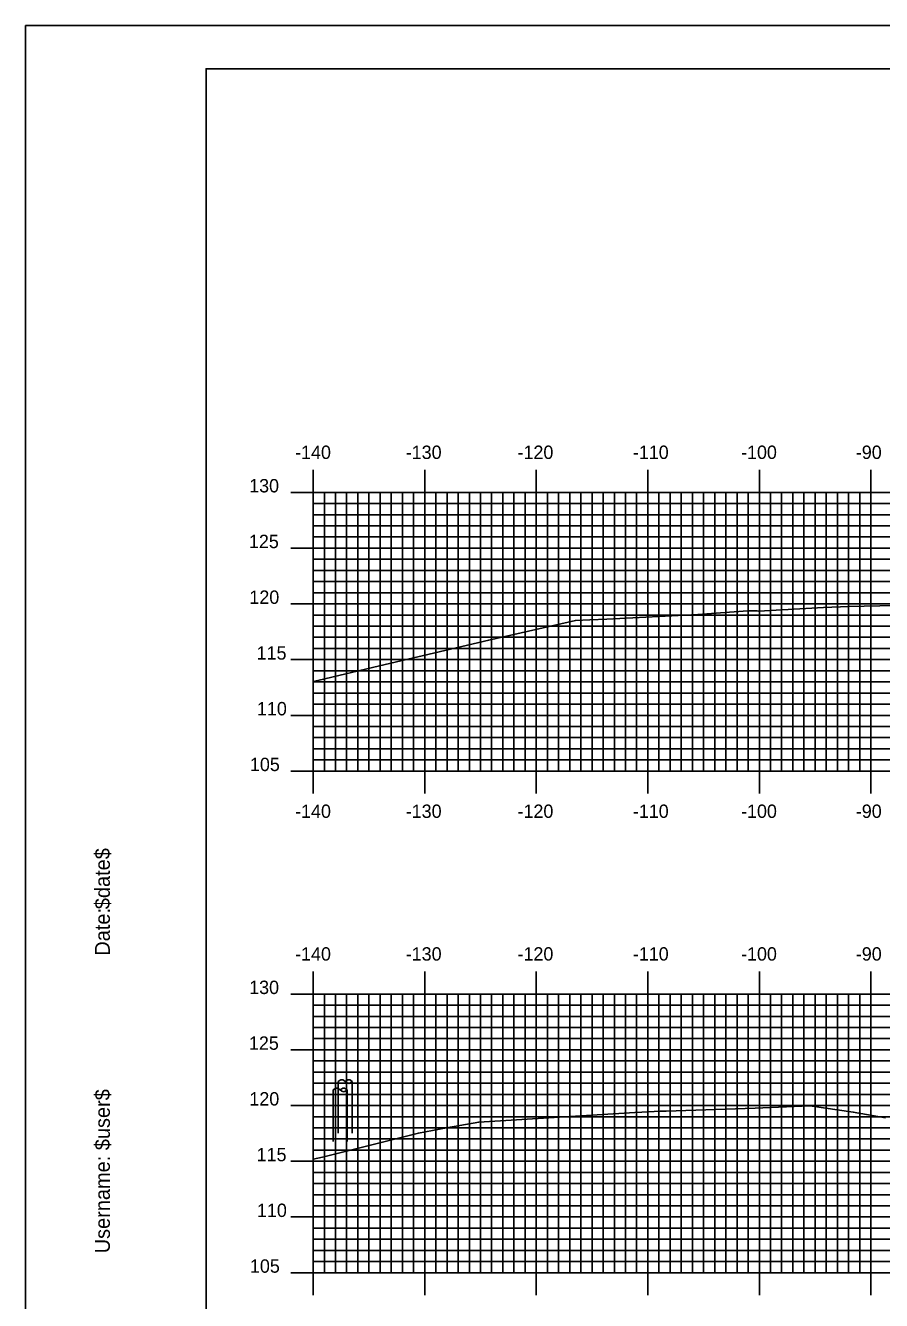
# Model space of a CAD drawing. Extents: x 1685979 to 1686323, y 461260 to 461480.
# Drawn here: x 1685979.5 to 1686056.2, y 461365.6 to 461480 of the extents above; entities that cross this region are included whole.
import ezdxf

# ---------------------------------------------------------------- set-up
doc = ezdxf.new("R2010")
doc.units = 0
for name, color, linetype in [('BORDER', 7, 'Continuous'), ('H_V ANNOTATION', 7, 'Continuous'), ('M_Roadway_Centerline', 7, 'Continuous'), ('M_Utilities_Pole_StreetLight', 7, 'Continuous'), ('MAJOR', 7, 'Continuous'), ('MINOR', 7, 'Continuous'), ('PLOT BOUNDARY', 7, 'Continuous'), ('S_Roadway_Centerline', 7, 'Continuous'), ('S_Utilities_Pole_StreetLight', 7, 'Continuous')]:
    doc.layers.add(name, color=color, linetype=linetype)

msp = doc.modelspace()

# ---------------------------------------------------------------- linework, layer by layer
at = {"layer": 'BORDER'}
msp.add_lwpolyline([(1685995.66, 461266.07), (1686315.66, 461266.07), (1686315.66, 461476.07), (1685995.66, 461476.07)], close=True, dxfattribs=at)
at = {"layer": 'M_Utilities_Pole_StreetLight'}
for p, q in [((1686007.05, 461384.47), (1686007.21, 461384.58)), ((1686007.05, 461379.85), (1686007.05, 461384.47)), ((1686007.52, 461384.58), (1686007.68, 461384.47)), ((1686007.83, 461384.58), (1686007.68, 461384.47)), ((1686007.68, 461384.47), (1686007.83, 461384.36)), ((1686008.3, 461384.47), (1686008.15, 461384.58)), ((1686008.15, 461384.36), (1686008.3, 461384.47)), ((1686008.3, 461379.85), (1686008.3, 461384.47))]:
    msp.add_line(p, q, dxfattribs=at)
for centre, start, end in [((1686007.36, 461384.36), 90, 125.2644), ((1686007.36, 461384.36), 54.7356, 90), ((1686007.99, 461384.36), 90, 125.2644), ((1686007.99, 461384.36), 54.7356, 90), ((1686007.99, 461384.58), 234.7356, 270), ((1686007.99, 461384.58), 270, 305.2644)]:
    msp.add_arc(centre, 0.271, start, end, dxfattribs=at)
at = {"layer": 'MAJOR'}
for p, q in [((1686005.26, 461440.08), (1686005.26, 461438.07)), ((1686015.26, 461440.08), (1686015.26, 461438.07)), ((1686025.26, 461440.08), (1686025.26, 461438.07)), ((1686035.26, 461440.08), (1686035.26, 461438.07)), ((1686045.26, 461440.08), (1686045.26, 461438.07)), ((1686055.26, 461440.08), (1686055.26, 461438.07)), ((1686003.25, 461438.07), (1686005.26, 461438.07)), ((1686005.26, 461438.07), (1686285.26, 461438.07)), ((1686005.26, 461413.07), (1686005.26, 461438.07)), ((1686005.26, 461413.07), (1686005.26, 461438.07)), ((1686005.26, 461438.07), (1686285.26, 461438.07)), ((1686015.26, 461413.07), (1686015.26, 461438.07)), ((1686025.26, 461413.07), (1686025.26, 461438.07)), ((1686035.26, 461413.07), (1686035.26, 461438.07)), ((1686045.26, 461413.07), (1686045.26, 461438.07)), ((1686055.26, 461413.07), (1686055.26, 461438.07)), ((1686003.25, 461433.07), (1686005.26, 461433.07)), ((1686005.26, 461433.07), (1686285.26, 461433.07)), ((1686003.25, 461428.07), (1686005.26, 461428.07)), ((1686005.26, 461428.07), (1686285.26, 461428.07)), ((1686003.25, 461423.07), (1686005.26, 461423.07)), ((1686005.26, 461423.07), (1686285.26, 461423.07)), ((1686003.25, 461418.07), (1686005.26, 461418.07)), ((1686005.26, 461418.07), (1686285.26, 461418.07)), ((1686003.25, 461413.07), (1686005.26, 461413.07)), ((1686005.26, 461413.07), (1686285.26, 461413.07)), ((1686005.26, 461413.07), (1686285.26, 461413.07)), ((1686005.26, 461411.07), (1686005.26, 461413.07)), ((1686015.26, 461411.07), (1686015.26, 461413.07)), ((1686025.26, 461411.07), (1686025.26, 461413.07)), ((1686035.26, 461411.07), (1686035.26, 461413.07)), ((1686045.26, 461411.07), (1686045.26, 461413.07)), ((1686055.26, 461411.07), (1686055.26, 461413.07)), ((1686005.26, 461395.08), (1686005.26, 461393.07)), ((1686015.26, 461395.08), (1686015.26, 461393.07)), ((1686025.26, 461395.08), (1686025.26, 461393.07)), ((1686035.26, 461395.08), (1686035.26, 461393.07)), ((1686045.26, 461395.08), (1686045.26, 461393.07)), ((1686055.26, 461395.08), (1686055.26, 461393.07)), ((1686003.25, 461393.07), (1686005.26, 461393.07)), ((1686005.26, 461393.07), (1686285.26, 461393.07)), ((1686005.26, 461368.07), (1686005.26, 461393.07)), ((1686005.26, 461368.07), (1686005.26, 461393.07)), ((1686005.26, 461393.07), (1686285.26, 461393.07)), ((1686015.26, 461368.07), (1686015.26, 461393.07)), ((1686025.26, 461368.07), (1686025.26, 461393.07)), ((1686035.26, 461368.07), (1686035.26, 461393.07)), ((1686045.26, 461368.07), (1686045.26, 461393.07)), ((1686055.26, 461368.07), (1686055.26, 461393.07)), ((1686003.25, 461388.07), (1686005.26, 461388.07)), ((1686005.26, 461388.07), (1686285.26, 461388.07)), ((1686003.25, 461383.07), (1686005.26, 461383.07)), ((1686005.26, 461383.07), (1686285.26, 461383.07)), ((1686003.25, 461378.07), (1686005.26, 461378.07)), ((1686005.26, 461378.07), (1686285.26, 461378.07)), ((1686003.25, 461373.07), (1686005.26, 461373.07)), ((1686005.26, 461373.07), (1686285.26, 461373.07)), ((1686003.25, 461368.07), (1686005.26, 461368.07)), ((1686005.26, 461368.07), (1686285.26, 461368.07)), ((1686005.26, 461368.07), (1686285.26, 461368.07)), ((1686005.26, 461366.07), (1686005.26, 461368.07)), ((1686015.26, 461366.07), (1686015.26, 461368.07)), ((1686025.26, 461366.07), (1686025.26, 461368.07)), ((1686035.26, 461366.07), (1686035.26, 461368.07)), ((1686045.26, 461366.07), (1686045.26, 461368.07)), ((1686055.26, 461366.07), (1686055.26, 461368.07))]:
    msp.add_line(p, q, dxfattribs=at)
at = {"layer": 'MINOR'}
for p, q in [((1686005.26, 461437.07), (1686285.26, 461437.07)), ((1686005.26, 461437.07), (1686007.26, 461437.07)), ((1686006.26, 461413.07), (1686006.26, 461438.07)), ((1686007.26, 461413.07), (1686007.26, 461438.07)), ((1686008.26, 461413.07), (1686008.26, 461438.07)), ((1686009.26, 461413.07), (1686009.26, 461438.07)), ((1686010.26, 461413.07), (1686010.26, 461438.07)), ((1686011.26, 461413.07), (1686011.26, 461438.07)), ((1686012.26, 461413.07), (1686012.26, 461438.07)), ((1686013.26, 461413.07), (1686013.26, 461438.07)), ((1686014.26, 461413.07), (1686014.26, 461438.07)), ((1686016.26, 461413.07), (1686016.26, 461438.07)), ((1686017.26, 461413.07), (1686017.26, 461438.07)), ((1686018.26, 461413.07), (1686018.26, 461438.07)), ((1686019.26, 461413.07), (1686019.26, 461438.07)), ((1686020.26, 461413.07), (1686020.26, 461438.07)), ((1686021.26, 461413.07), (1686021.26, 461438.07)), ((1686022.26, 461413.07), (1686022.26, 461438.07)), ((1686023.26, 461413.07), (1686023.26, 461438.07)), ((1686024.26, 461413.07), (1686024.26, 461438.07)), ((1686026.26, 461413.07), (1686026.26, 461438.07)), ((1686027.26, 461413.07), (1686027.26, 461438.07)), ((1686028.26, 461413.07), (1686028.26, 461438.07)), ((1686029.26, 461413.07), (1686029.26, 461438.07)), ((1686030.26, 461413.07), (1686030.26, 461438.07)), ((1686031.26, 461413.07), (1686031.26, 461438.07)), ((1686032.26, 461413.07), (1686032.26, 461438.07)), ((1686033.26, 461413.07), (1686033.26, 461438.07)), ((1686034.26, 461413.07), (1686034.26, 461438.07)), ((1686036.26, 461413.07), (1686036.26, 461438.07)), ((1686037.26, 461413.07), (1686037.26, 461438.07)), ((1686038.26, 461413.07), (1686038.26, 461438.07)), ((1686039.26, 461413.07), (1686039.26, 461438.07)), ((1686040.26, 461413.07), (1686040.26, 461438.07)), ((1686041.26, 461413.07), (1686041.26, 461438.07)), ((1686042.26, 461413.07), (1686042.26, 461438.07)), ((1686043.26, 461413.07), (1686043.26, 461438.07)), ((1686044.26, 461413.07), (1686044.26, 461438.07)), ((1686046.26, 461413.07), (1686046.26, 461438.07)), ((1686047.26, 461413.07), (1686047.26, 461438.07)), ((1686048.26, 461413.07), (1686048.26, 461438.07)), ((1686049.26, 461413.07), (1686049.26, 461438.07)), ((1686050.26, 461413.07), (1686050.26, 461438.07)), ((1686051.26, 461413.07), (1686051.26, 461438.07)), ((1686052.26, 461413.07), (1686052.26, 461438.07)), ((1686053.26, 461413.07), (1686053.26, 461438.07)), ((1686054.26, 461413.07), (1686054.26, 461438.07)), ((1686005.26, 461436.07), (1686285.26, 461436.07)), ((1686005.26, 461436.07), (1686007.26, 461436.07)), ((1686005.26, 461435.07), (1686285.26, 461435.07)), ((1686005.26, 461435.07), (1686007.26, 461435.07)), ((1686005.26, 461434.07), (1686285.26, 461434.07)), ((1686005.26, 461434.07), (1686007.26, 461434.07)), ((1686005.26, 461432.07), (1686285.26, 461432.07)), ((1686005.26, 461432.07), (1686007.26, 461432.07)), ((1686005.26, 461431.07), (1686285.26, 461431.07)), ((1686005.26, 461431.07), (1686007.26, 461431.07)), ((1686005.26, 461430.07), (1686285.26, 461430.07)), ((1686005.26, 461430.07), (1686007.26, 461430.07)), ((1686005.26, 461429.07), (1686285.26, 461429.07)), ((1686005.26, 461429.07), (1686007.26, 461429.07)), ((1686005.26, 461427.07), (1686285.26, 461427.07)), ((1686005.26, 461427.07), (1686007.26, 461427.07)), ((1686005.26, 461426.07), (1686285.26, 461426.07)), ((1686005.26, 461426.07), (1686007.26, 461426.07)), ((1686005.26, 461425.07), (1686007.26, 461425.07)), ((1686005.26, 461425.07), (1686285.26, 461425.07)), ((1686005.26, 461424.07), (1686285.26, 461424.07)), ((1686005.26, 461424.07), (1686007.26, 461424.07)), ((1686005.26, 461422.07), (1686285.26, 461422.07)), ((1686005.26, 461422.07), (1686007.26, 461422.07)), ((1686005.26, 461421.07), (1686285.26, 461421.07)), ((1686005.26, 461421.07), (1686007.26, 461421.07)), ((1686005.26, 461420.07), (1686285.26, 461420.07)), ((1686005.26, 461420.07), (1686007.26, 461420.07)), ((1686005.26, 461419.07), (1686285.26, 461419.07)), ((1686005.26, 461419.07), (1686007.26, 461419.07)), ((1686005.26, 461417.07), (1686285.26, 461417.07)), ((1686005.26, 461417.07), (1686007.26, 461417.07)), ((1686005.26, 461416.07), (1686285.26, 461416.07)), ((1686005.26, 461416.07), (1686007.26, 461416.07)), ((1686005.26, 461415.07), (1686285.26, 461415.07)), ((1686005.26, 461415.07), (1686007.26, 461415.07)), ((1686005.26, 461414.07), (1686285.26, 461414.07)), ((1686005.26, 461414.07), (1686007.26, 461414.07)), ((1686006.26, 461368.07), (1686006.26, 461393.07)), ((1686007.26, 461368.07), (1686007.26, 461393.07)), ((1686008.26, 461368.07), (1686008.26, 461393.07)), ((1686009.26, 461368.07), (1686009.26, 461393.07)), ((1686010.26, 461368.07), (1686010.26, 461393.07)), ((1686011.26, 461368.07), (1686011.26, 461393.07)), ((1686012.26, 461368.07), (1686012.26, 461393.07)), ((1686013.26, 461368.07), (1686013.26, 461393.07)), ((1686014.26, 461368.07), (1686014.26, 461393.07)), ((1686016.26, 461368.07), (1686016.26, 461393.07)), ((1686017.26, 461368.07), (1686017.26, 461393.07)), ((1686018.26, 461368.07), (1686018.26, 461393.07)), ((1686019.26, 461368.07), (1686019.26, 461393.07)), ((1686020.26, 461368.07), (1686020.26, 461393.07)), ((1686021.26, 461368.07), (1686021.26, 461393.07)), ((1686022.26, 461368.07), (1686022.26, 461393.07)), ((1686023.26, 461368.07), (1686023.26, 461393.07)), ((1686024.26, 461368.07), (1686024.26, 461393.07)), ((1686026.26, 461368.07), (1686026.26, 461393.07)), ((1686027.26, 461368.07), (1686027.26, 461393.07)), ((1686028.26, 461368.07), (1686028.26, 461393.07)), ((1686029.26, 461368.07), (1686029.26, 461393.07)), ((1686030.26, 461368.07), (1686030.26, 461393.07)), ((1686031.26, 461368.07), (1686031.26, 461393.07)), ((1686032.26, 461368.07), (1686032.26, 461393.07)), ((1686033.26, 461368.07), (1686033.26, 461393.07)), ((1686034.26, 461368.07), (1686034.26, 461393.07)), ((1686036.26, 461368.07), (1686036.26, 461393.07)), ((1686037.26, 461368.07), (1686037.26, 461393.07)), ((1686038.26, 461368.07), (1686038.26, 461393.07)), ((1686039.26, 461368.07), (1686039.26, 461393.07)), ((1686040.26, 461368.07), (1686040.26, 461393.07)), ((1686041.26, 461368.07), (1686041.26, 461393.07)), ((1686042.26, 461368.07), (1686042.26, 461393.07)), ((1686043.26, 461368.07), (1686043.26, 461393.07)), ((1686044.26, 461368.07), (1686044.26, 461393.07)), ((1686046.26, 461368.07), (1686046.26, 461393.07)), ((1686047.26, 461368.07), (1686047.26, 461393.07)), ((1686048.26, 461368.07), (1686048.26, 461393.07)), ((1686049.26, 461368.07), (1686049.26, 461393.07)), ((1686050.26, 461368.07), (1686050.26, 461393.07)), ((1686051.26, 461368.07), (1686051.26, 461393.07)), ((1686052.26, 461368.07), (1686052.26, 461393.07)), ((1686053.26, 461368.07), (1686053.26, 461393.07)), ((1686054.26, 461368.07), (1686054.26, 461393.07)), ((1686005.26, 461392.07), (1686285.26, 461392.07)), ((1686005.26, 461392.07), (1686007.26, 461392.07)), ((1686005.26, 461391.07), (1686285.26, 461391.07)), ((1686005.26, 461391.07), (1686007.26, 461391.07)), ((1686005.26, 461390.07), (1686285.26, 461390.07)), ((1686005.26, 461390.07), (1686007.26, 461390.07)), ((1686005.26, 461389.07), (1686285.26, 461389.07)), ((1686005.26, 461389.07), (1686007.26, 461389.07)), ((1686005.26, 461387.07), (1686285.26, 461387.07)), ((1686005.26, 461387.07), (1686007.26, 461387.07)), ((1686005.26, 461386.07), (1686285.26, 461386.07)), ((1686005.26, 461386.07), (1686007.26, 461386.07)), ((1686005.26, 461385.07), (1686285.26, 461385.07)), ((1686005.26, 461385.07), (1686007.26, 461385.07)), ((1686005.26, 461384.07), (1686285.26, 461384.07)), ((1686005.26, 461384.07), (1686007.26, 461384.07)), ((1686005.26, 461382.07), (1686285.26, 461382.07)), ((1686005.26, 461382.07), (1686007.26, 461382.07)), ((1686005.26, 461381.07), (1686285.26, 461381.07)), ((1686005.26, 461381.07), (1686007.26, 461381.07)), ((1686005.26, 461380.07), (1686285.26, 461380.07)), ((1686005.26, 461380.07), (1686007.26, 461380.07)), ((1686005.26, 461379.07), (1686285.26, 461379.07)), ((1686005.26, 461379.07), (1686007.26, 461379.07)), ((1686005.26, 461377.07), (1686285.26, 461377.07)), ((1686005.26, 461377.07), (1686007.26, 461377.07)), ((1686005.26, 461376.07), (1686285.26, 461376.07)), ((1686005.26, 461376.07), (1686007.26, 461376.07)), ((1686005.26, 461375.07), (1686285.26, 461375.07)), ((1686005.26, 461375.07), (1686007.26, 461375.07)), ((1686005.26, 461374.07), (1686285.26, 461374.07)), ((1686005.26, 461374.07), (1686007.26, 461374.07)), ((1686005.26, 461372.07), (1686285.26, 461372.07)), ((1686005.26, 461372.07), (1686007.26, 461372.07)), ((1686005.26, 461371.07), (1686285.26, 461371.07)), ((1686005.26, 461371.07), (1686007.26, 461371.07)), ((1686005.26, 461370.07), (1686285.26, 461370.07)), ((1686005.26, 461370.07), (1686007.26, 461370.07)), ((1686005.26, 461369.07), (1686285.26, 461369.07)), ((1686005.26, 461369.07), (1686007.26, 461369.07))]:
    msp.add_line(p, q, dxfattribs=at)
at = {"layer": 'PLOT BOUNDARY'}
msp.add_lwpolyline([(1685979.47, 461259.95), (1686319.47, 461259.95), (1686319.47, 461479.95), (1685979.47, 461479.95)], close=True, dxfattribs=at)
at = {"layer": 'S_Roadway_Centerline'}
for points in [[(1686005.26, 461421.11), (1686005.69, 461421.2), (1686011.2, 461422.52), (1686021, 461424.82), (1686028.77, 461426.58), (1686030.05, 461426.63), (1686031.6, 461426.7), (1686039.75, 461427.13), (1686044.23, 461427.46), (1686045.05, 461427.44), (1686045.19, 461427.42), (1686051, 461427.74), (1686053.29, 461427.84), (1686057.45, 461427.93)], [(1686005.26, 461378.25), (1686006.09, 461378.45), (1686014.7, 461380.59), (1686017.22, 461381.07), (1686020.11, 461381.59), (1686034.1, 461382.43), (1686034.72, 461382.47), (1686036.37, 461382.57), (1686036.92, 461382.57), (1686044.87, 461382.83), (1686049.79, 461383.03), (1686053.68, 461382.48), (1686056.57, 461381.96)]]:
    msp.add_lwpolyline(points, dxfattribs=at)
at = {"layer": 'S_Utilities_Pole_StreetLight'}
for p, q in [((1686007.51, 461385.22), (1686007.67, 461385.33)), ((1686007.51, 461385.22), (1686007.67, 461385.33)), ((1686007.51, 461380.6), (1686007.51, 461385.22)), ((1686007.51, 461380.6), (1686007.51, 461385.22)), ((1686007.98, 461385.33), (1686008.14, 461385.22)), ((1686007.98, 461385.33), (1686008.14, 461385.22)), ((1686008.3, 461385.33), (1686008.14, 461385.22)), ((1686008.3, 461385.33), (1686008.14, 461385.22)), ((1686008.14, 461385.22), (1686008.3, 461385.11)), ((1686008.14, 461385.22), (1686008.3, 461385.11)), ((1686008.76, 461385.22), (1686008.61, 461385.33)), ((1686008.76, 461385.22), (1686008.61, 461385.33)), ((1686008.61, 461385.11), (1686008.76, 461385.22)), ((1686008.61, 461385.11), (1686008.76, 461385.22)), ((1686008.76, 461380.6), (1686008.76, 461385.22)), ((1686008.76, 461380.6), (1686008.76, 461385.22))]:
    msp.add_line(p, q, dxfattribs=at)
for centre, start, end in [((1686007.83, 461385.11), 90, 125.2644), ((1686007.83, 461385.11), 90, 125.2644), ((1686007.83, 461385.11), 54.7356, 90), ((1686007.83, 461385.11), 54.7356, 90), ((1686008.45, 461385.11), 90, 125.2644), ((1686008.45, 461385.11), 90, 125.2644), ((1686008.45, 461385.33), 234.7356, 270), ((1686008.45, 461385.33), 234.7356, 270), ((1686008.45, 461385.11), 54.7356, 90), ((1686008.45, 461385.11), 54.7356, 90), ((1686008.45, 461385.33), 270, 305.2644), ((1686008.45, 461385.33), 270, 305.2644)]:
    msp.add_arc(centre, 0.271, start, end, dxfattribs=at)

# ---------------------------------------------------------------- texts
at = {"layer": 'BORDER'}
for s, p in [('$date$', (1685987.03, 461400.68)), ('Date:', (1685987.03, 461396.51)), ('$user$', (1685987.03, 461379.06)), ('Username:', (1685987.03, 461369.81))]:
    msp.add_text(s, height=1.339, rotation=90, dxfattribs=at).set_placement(p)
at = {"layer": 'H_V ANNOTATION'}
for s, p in [('-140', (1686003.64, 461441.07)), ('-130', (1686013.56, 461441.07)), ('-120', (1686023.58, 461441.07)), ('-110', (1686033.92, 461441.07)), ('-100', (1686043.62, 461441.07)), ('-90', (1686053.91, 461441.07)), ('130', (1685999.52, 461438.07)), ('125', (1685999.5, 461433.07)), ('120', (1685999.54, 461428.07)), ('115', (1686000.19, 461423.07)), ('110', (1686000.22, 461418.07)), ('105', (1685999.59, 461413.07)), ('-140', (1686003.64, 461408.87)), ('-130', (1686013.56, 461408.87)), ('-120', (1686023.58, 461408.87)), ('-110', (1686033.92, 461408.87)), ('-100', (1686043.62, 461408.87)), ('-90', (1686053.91, 461408.87)), ('-140', (1686003.64, 461396.07)), ('-130', (1686013.56, 461396.07)), ('-120', (1686023.58, 461396.07)), ('-110', (1686033.92, 461396.07)), ('-100', (1686043.62, 461396.07)), ('-90', (1686053.91, 461396.07)), ('130', (1685999.52, 461393.07)), ('125', (1685999.5, 461388.07)), ('120', (1685999.54, 461383.07)), ('115', (1686000.19, 461378.07)), ('110', (1686000.22, 461373.07)), ('105', (1685999.59, 461368.07))]:
    msp.add_text(s, height=1.2, dxfattribs=at).set_placement(p)
at = {"layer": 'M_Roadway_Centerline'}
for s, p in [('C', (1686044.23, 461427.46)), ('L', (1686044.23, 461427.45)), ('C', (1686036.37, 461382.57)), ('L', (1686036.37, 461382.56))]:
    msp.add_text(s, height=0.0146, dxfattribs=at).set_placement(p)
at = {"layer": 'MAJOR'}
for p in [(1686005.25, 461413.07), (1686005.25, 461368.07)]:
    msp.add_text('-', height=0.012, dxfattribs=at).set_placement(p)

doc.saveas('drawing.dxf')
